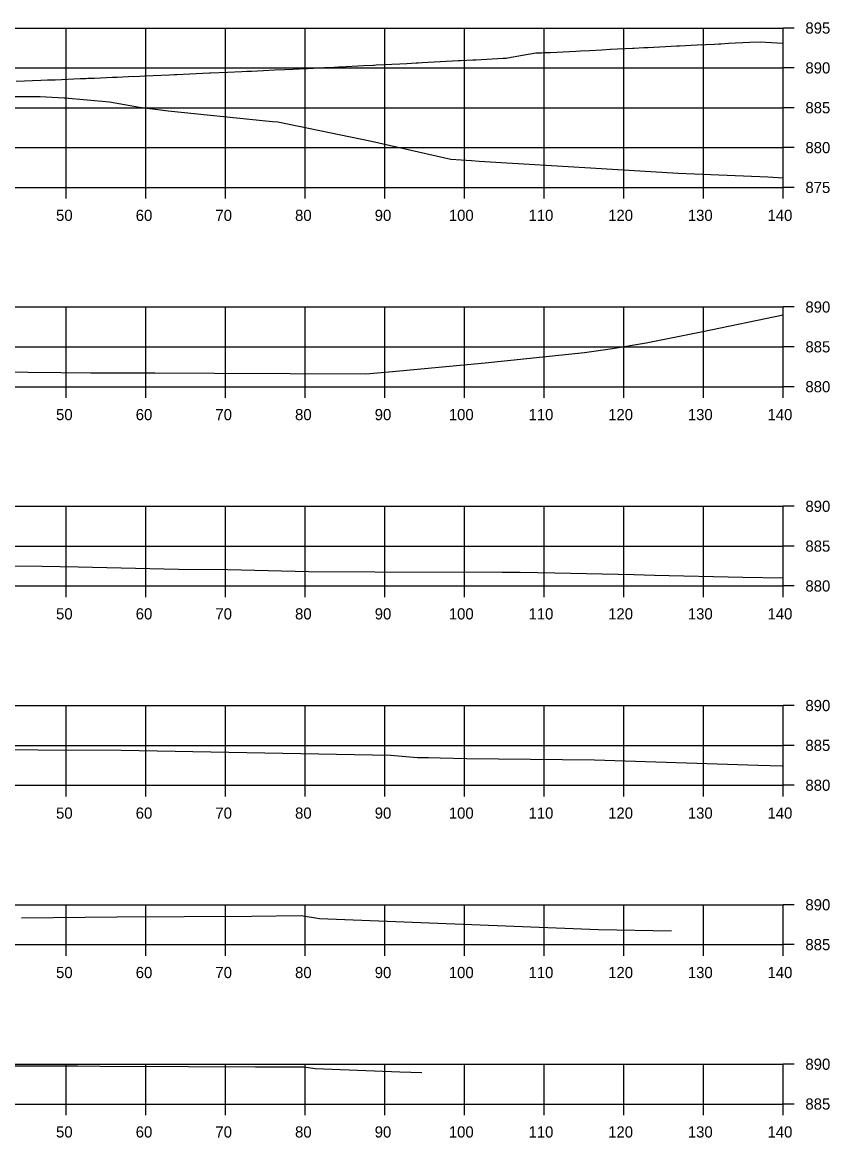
# Model space of a CAD drawing. Extents: x 1098669 to 1198896, y 698679 to 704410.
# Drawn here: x 1110825.7 to 1110927, y 701504.9 to 701644.8 of the extents above; entities that cross this region are included whole.
import ezdxf

# ---------------------------------------------------------------- set-up
doc = ezdxf.new("R2010")
doc.units = 0
for name, color, linetype in [('Proposed Surface', 7, 'Continuous'), ('R_Axis', 7, 'Continuous'), ('R_Axis Annot', 7, 'Continuous'), ('R_Fin Surface', 7, 'Continuous'), ('R_Grid', 7, 'Continuous')]:
    doc.layers.add(name, color=color, linetype=linetype)

msp = doc.modelspace()

# ---------------------------------------------------------------- linework, layer by layer
at = {"layer": 'Proposed Surface'}
for points in [[(1110817.22, 701635.54), (1110827.92, 701635.53), (1110830.92, 701635.39), (1110830.94, 701635.39), (1110831, 701635.38), (1110836.59, 701634.87), (1110840.38, 701634.2), (1110843.97, 701633.73), (1110856.25, 701632.5), (1110857.09, 701632.4), (1110857.75, 701632.37), (1110869.48, 701629.95), (1110879.45, 701627.66), (1110882.06, 701627.52), (1110883.01, 701627.44), (1110898.35, 701626.52), (1110908.01, 701625.93), (1110919.25, 701625.46), (1110921.16, 701625.35)], [(1110818.1, 701601.03), (1110826.42, 701600.95), (1110830.49, 701600.91), (1110834.28, 701600.89), (1110842.32, 701600.86), (1110849.78, 701600.82), (1110868.77, 701600.75), (1110870.23, 701600.87), (1110871.69, 701601.01), (1110883.76, 701602.12), (1110896.24, 701603.43), (1110899.73, 701603.92), (1110903.98, 701604.64), (1110911.07, 701606.06), (1110921.16, 701608.16)], [(1110805.54, 701576.75), (1110828.16, 701576.6), (1110832.68, 701576.55), (1110845.26, 701576.24), (1110851.45, 701576.18), (1110861.57, 701575.94), (1110869.92, 701575.91), (1110885.89, 701575.86), (1110888.15, 701575.85), (1110892.5, 701575.79), (1110902.42, 701575.55), (1110905.02, 701575.5), (1110916.12, 701575.24), (1110921.16, 701575.14)], [(1110817.14, 701553.61), (1110838.07, 701553.53), (1110871.9, 701552.9), (1110875.26, 701552.62), (1110876.64, 701552.61), (1110878.11, 701552.57), (1110881.41, 701552.48), (1110897.47, 701552.3), (1110918.01, 701551.63), (1110921.05, 701551.56), (1110921.16, 701551.56)], [(1110825.58, 701532.51), (1110837.52, 701532.63), (1110854.44, 701532.69), (1110860.66, 701532.77), (1110862.96, 701532.42), (1110898.01, 701531.02), (1110907.14, 701530.86)], [(1110820.41, 701513.93), (1110832.6, 701513.91), (1110835.45, 701513.88), (1110846.52, 701513.83), (1110854.92, 701513.81), (1110861.01, 701513.79), (1110862.44, 701513.57), (1110873.07, 701513.15), (1110875.83, 701513.1)]]:
    msp.add_lwpolyline(points, dxfattribs=at)
at = {"layer": 'R_Axis'}
for p, q in [((1110921.16, 701624.13), (1110921.16, 701644.13)), ((1110922.56, 701644.13), (1110921.16, 701644.13)), ((1110922.56, 701639.13), (1110921.16, 701639.13)), ((1110922.56, 701634.13), (1110921.16, 701634.13)), ((1110922.56, 701629.13), (1110921.16, 701629.13)), ((1110641.16, 701624.13), (1110921.16, 701624.13)), ((1110831.16, 701622.73), (1110831.16, 701624.13)), ((1110841.16, 701622.73), (1110841.16, 701624.13)), ((1110851.16, 701622.73), (1110851.16, 701624.13)), ((1110861.16, 701622.73), (1110861.16, 701624.13)), ((1110871.16, 701622.73), (1110871.16, 701624.13)), ((1110881.16, 701622.73), (1110881.16, 701624.13)), ((1110891.16, 701622.73), (1110891.16, 701624.13)), ((1110901.16, 701622.73), (1110901.16, 701624.13)), ((1110911.16, 701622.73), (1110911.16, 701624.13)), ((1110921.16, 701622.73), (1110921.16, 701624.13)), ((1110922.56, 701624.13), (1110921.16, 701624.13)), ((1110921.16, 701599.13), (1110921.16, 701609.13)), ((1110922.56, 701609.13), (1110921.16, 701609.13)), ((1110922.56, 701604.13), (1110921.16, 701604.13)), ((1110641.16, 701599.13), (1110921.16, 701599.13)), ((1110831.16, 701597.73), (1110831.16, 701599.13)), ((1110841.16, 701597.73), (1110841.16, 701599.13)), ((1110851.16, 701597.73), (1110851.16, 701599.13)), ((1110861.16, 701597.73), (1110861.16, 701599.13)), ((1110871.16, 701597.73), (1110871.16, 701599.13)), ((1110881.16, 701597.73), (1110881.16, 701599.13)), ((1110891.16, 701597.73), (1110891.16, 701599.13)), ((1110901.16, 701597.73), (1110901.16, 701599.13)), ((1110911.16, 701597.73), (1110911.16, 701599.13)), ((1110921.16, 701597.73), (1110921.16, 701599.13)), ((1110922.56, 701599.13), (1110921.16, 701599.13)), ((1110921.16, 701574.13), (1110921.16, 701584.13)), ((1110922.56, 701584.13), (1110921.16, 701584.13)), ((1110922.56, 701579.13), (1110921.16, 701579.13)), ((1110641.16, 701574.13), (1110921.16, 701574.13)), ((1110831.16, 701572.73), (1110831.16, 701574.13)), ((1110841.16, 701572.73), (1110841.16, 701574.13)), ((1110851.16, 701572.73), (1110851.16, 701574.13)), ((1110861.16, 701572.73), (1110861.16, 701574.13)), ((1110871.16, 701572.73), (1110871.16, 701574.13)), ((1110881.16, 701572.73), (1110881.16, 701574.13)), ((1110891.16, 701572.73), (1110891.16, 701574.13)), ((1110901.16, 701572.73), (1110901.16, 701574.13)), ((1110911.16, 701572.73), (1110911.16, 701574.13)), ((1110921.16, 701572.73), (1110921.16, 701574.13)), ((1110922.56, 701574.13), (1110921.16, 701574.13)), ((1110921.16, 701549.13), (1110921.16, 701559.13)), ((1110922.56, 701559.13), (1110921.16, 701559.13)), ((1110922.56, 701554.13), (1110921.16, 701554.13)), ((1110641.16, 701549.13), (1110921.16, 701549.13)), ((1110831.16, 701547.73), (1110831.16, 701549.13)), ((1110841.16, 701547.73), (1110841.16, 701549.13)), ((1110851.16, 701547.73), (1110851.16, 701549.13)), ((1110861.16, 701547.73), (1110861.16, 701549.13)), ((1110871.16, 701547.73), (1110871.16, 701549.13)), ((1110881.16, 701547.73), (1110881.16, 701549.13)), ((1110891.16, 701547.73), (1110891.16, 701549.13)), ((1110901.16, 701547.73), (1110901.16, 701549.13)), ((1110911.16, 701547.73), (1110911.16, 701549.13)), ((1110921.16, 701547.73), (1110921.16, 701549.13)), ((1110922.56, 701549.13), (1110921.16, 701549.13)), ((1110921.16, 701529.13), (1110921.16, 701534.13)), ((1110922.56, 701534.13), (1110921.16, 701534.13)), ((1110641.16, 701529.13), (1110921.16, 701529.13)), ((1110831.16, 701527.73), (1110831.16, 701529.13)), ((1110841.16, 701527.73), (1110841.16, 701529.13)), ((1110851.16, 701527.73), (1110851.16, 701529.13)), ((1110861.16, 701527.73), (1110861.16, 701529.13)), ((1110871.16, 701527.73), (1110871.16, 701529.13)), ((1110881.16, 701527.73), (1110881.16, 701529.13)), ((1110891.16, 701527.73), (1110891.16, 701529.13)), ((1110901.16, 701527.73), (1110901.16, 701529.13)), ((1110911.16, 701527.73), (1110911.16, 701529.13)), ((1110921.16, 701527.73), (1110921.16, 701529.13)), ((1110922.56, 701529.13), (1110921.16, 701529.13)), ((1110921.16, 701509.13), (1110921.16, 701514.13)), ((1110922.56, 701514.13), (1110921.16, 701514.13)), ((1110641.16, 701509.13), (1110921.16, 701509.13)), ((1110831.16, 701507.73), (1110831.16, 701509.13)), ((1110841.16, 701507.73), (1110841.16, 701509.13)), ((1110851.16, 701507.73), (1110851.16, 701509.13)), ((1110861.16, 701507.73), (1110861.16, 701509.13)), ((1110871.16, 701507.73), (1110871.16, 701509.13)), ((1110881.16, 701507.73), (1110881.16, 701509.13)), ((1110891.16, 701507.73), (1110891.16, 701509.13)), ((1110901.16, 701507.73), (1110901.16, 701509.13)), ((1110911.16, 701507.73), (1110911.16, 701509.13)), ((1110921.16, 701507.73), (1110921.16, 701509.13)), ((1110922.56, 701509.13), (1110921.16, 701509.13))]:
    msp.add_line(p, q, dxfattribs=at)
at = {"layer": 'R_Fin Surface'}
msp.add_lwpolyline([(1110824.9, 701637.45), (1110828.01, 701637.58), (1110828.82, 701637.61), (1110828.84, 701637.61), (1110828.91, 701637.61), (1110829.81, 701637.65), (1110832.94, 701637.78), (1110833.66, 701637.81), (1110833.91, 701637.82), (1110834.73, 701637.85), (1110836.97, 701637.95), (1110837.58, 701637.97), (1110839.01, 701638.03), (1110840.36, 701638.09), (1110841.02, 701638.12), (1110842.1, 701638.17), (1110844.13, 701638.26), (1110844.72, 701638.29), (1110845.08, 701638.3), (1110846.71, 701638.38), (1110849.15, 701638.49), (1110849.2, 701638.49), (1110849.27, 701638.49), (1110851.42, 701638.59), (1110853.24, 701638.68), (1110853.85, 701638.71), (1110854.44, 701638.73), (1110855.94, 701638.8), (1110857.34, 701638.87), (1110858.61, 701638.93), (1110859.63, 701638.98), (1110860.4, 701639.02), (1110861.46, 701639.07), (1110863.58, 701639.17), (1110864.85, 701639.24), (1110865.34, 701639.26), (1110865.6, 701639.27), (1110868.51, 701639.42), (1110869.76, 701639.48), (1110869.85, 701639.49), (1110870.09, 701639.5), (1110873.06, 701639.65), (1110873.93, 701639.7), (1110875.09, 701639.76), (1110875.37, 701639.77), (1110875.87, 701639.8), (1110878.13, 701639.92), (1110880.41, 701640.04), (1110880.68, 701640.05), (1110882.22, 701640.13), (1110882.35, 701640.14), (1110882.59, 701640.15), (1110886.03, 701640.34), (1110886.03, 701640.34), (1110886.39, 701640.36), (1110886.58, 701640.39), (1110888.47, 701640.72), (1110890.14, 701641), (1110890.85, 701641.03), (1110891.12, 701641.05), (1110891.41, 701641.06), (1110891.79, 701641.08), (1110891.98, 701641.08), (1110895.14, 701641.24), (1110895.73, 701641.27), (1110896.84, 701641.33), (1110898.42, 701641.41), (1110899.45, 701641.46), (1110902.24, 701641.6), (1110902.3, 701641.61), (1110902.32, 701641.61), (1110902.46, 701641.61), (1110903.68, 701641.68), (1110903.79, 701641.68), (1110904.22, 701641.7), (1110907.81, 701641.88), (1110907.93, 701641.89), (1110908.16, 701641.9), (1110910.39, 701642.02), (1110912.55, 701642.12), (1110913.09, 701642.15), (1110913.36, 701642.16), (1110914.3, 701642.21), (1110916.98, 701642.35), (1110918.3, 701642.41), (1110918.96, 701642.37), (1110921.16, 701642.22)], dxfattribs=at)
at = {"layer": 'R_Grid'}
for p, q in [((1110641.16, 701644.13), (1110921.16, 701644.13)), ((1110831.16, 701624.13), (1110831.16, 701644.13)), ((1110841.16, 701624.13), (1110841.16, 701644.13)), ((1110851.16, 701624.13), (1110851.16, 701644.13)), ((1110861.16, 701624.13), (1110861.16, 701644.13)), ((1110871.16, 701624.13), (1110871.16, 701644.13)), ((1110881.16, 701624.13), (1110881.16, 701644.13)), ((1110891.16, 701624.13), (1110891.16, 701644.13)), ((1110901.16, 701624.13), (1110901.16, 701644.13)), ((1110911.16, 701624.13), (1110911.16, 701644.13)), ((1110921.16, 701624.13), (1110921.16, 701644.13)), ((1110641.16, 701639.13), (1110921.16, 701639.13)), ((1110641.16, 701634.13), (1110921.16, 701634.13)), ((1110641.16, 701629.13), (1110921.16, 701629.13)), ((1110641.16, 701624.13), (1110921.16, 701624.13)), ((1110641.16, 701609.13), (1110921.16, 701609.13)), ((1110831.16, 701599.13), (1110831.16, 701609.13)), ((1110841.16, 701599.13), (1110841.16, 701609.13)), ((1110851.16, 701599.13), (1110851.16, 701609.13)), ((1110861.16, 701599.13), (1110861.16, 701609.13)), ((1110871.16, 701599.13), (1110871.16, 701609.13)), ((1110881.16, 701599.13), (1110881.16, 701609.13)), ((1110891.16, 701599.13), (1110891.16, 701609.13)), ((1110901.16, 701599.13), (1110901.16, 701609.13)), ((1110911.16, 701599.13), (1110911.16, 701609.13)), ((1110921.16, 701599.13), (1110921.16, 701609.13)), ((1110641.16, 701604.13), (1110921.16, 701604.13)), ((1110641.16, 701599.13), (1110921.16, 701599.13)), ((1110641.16, 701584.13), (1110921.16, 701584.13)), ((1110831.16, 701574.13), (1110831.16, 701584.13)), ((1110841.16, 701574.13), (1110841.16, 701584.13)), ((1110851.16, 701574.13), (1110851.16, 701584.13)), ((1110861.16, 701574.13), (1110861.16, 701584.13)), ((1110871.16, 701574.13), (1110871.16, 701584.13)), ((1110881.16, 701574.13), (1110881.16, 701584.13)), ((1110891.16, 701574.13), (1110891.16, 701584.13)), ((1110901.16, 701574.13), (1110901.16, 701584.13)), ((1110911.16, 701574.13), (1110911.16, 701584.13)), ((1110921.16, 701574.13), (1110921.16, 701584.13)), ((1110641.16, 701579.13), (1110921.16, 701579.13)), ((1110641.16, 701574.13), (1110921.16, 701574.13)), ((1110641.16, 701559.13), (1110921.16, 701559.13)), ((1110831.16, 701549.13), (1110831.16, 701559.13)), ((1110841.16, 701549.13), (1110841.16, 701559.13)), ((1110851.16, 701549.13), (1110851.16, 701559.13)), ((1110861.16, 701549.13), (1110861.16, 701559.13)), ((1110871.16, 701549.13), (1110871.16, 701559.13)), ((1110881.16, 701549.13), (1110881.16, 701559.13)), ((1110891.16, 701549.13), (1110891.16, 701559.13)), ((1110901.16, 701549.13), (1110901.16, 701559.13)), ((1110911.16, 701549.13), (1110911.16, 701559.13)), ((1110921.16, 701549.13), (1110921.16, 701559.13)), ((1110641.16, 701554.13), (1110921.16, 701554.13)), ((1110641.16, 701549.13), (1110921.16, 701549.13)), ((1110641.16, 701534.13), (1110921.16, 701534.13)), ((1110831.16, 701529.13), (1110831.16, 701534.13)), ((1110841.16, 701529.13), (1110841.16, 701534.13)), ((1110851.16, 701529.13), (1110851.16, 701534.13)), ((1110861.16, 701529.13), (1110861.16, 701534.13)), ((1110871.16, 701529.13), (1110871.16, 701534.13)), ((1110881.16, 701529.13), (1110881.16, 701534.13)), ((1110891.16, 701529.13), (1110891.16, 701534.13)), ((1110901.16, 701529.13), (1110901.16, 701534.13)), ((1110911.16, 701529.13), (1110911.16, 701534.13)), ((1110921.16, 701529.13), (1110921.16, 701534.13)), ((1110641.16, 701529.13), (1110921.16, 701529.13)), ((1110641.16, 701514.13), (1110921.16, 701514.13)), ((1110831.16, 701509.13), (1110831.16, 701514.13)), ((1110841.16, 701509.13), (1110841.16, 701514.13)), ((1110851.16, 701509.13), (1110851.16, 701514.13)), ((1110861.16, 701509.13), (1110861.16, 701514.13)), ((1110871.16, 701509.13), (1110871.16, 701514.13)), ((1110881.16, 701509.13), (1110881.16, 701514.13)), ((1110891.16, 701509.13), (1110891.16, 701514.13)), ((1110901.16, 701509.13), (1110901.16, 701514.13)), ((1110911.16, 701509.13), (1110911.16, 701514.13)), ((1110921.16, 701509.13), (1110921.16, 701514.13)), ((1110641.16, 701509.13), (1110921.16, 701509.13))]:
    msp.add_line(p, q, dxfattribs=at)

# ---------------------------------------------------------------- texts
at = {"layer": 'R_Axis Annot'}
for s, p in [('895', (1110923.96, 701643.43)), ('890', (1110923.96, 701638.43)), ('885', (1110923.96, 701633.43)), ('880', (1110923.96, 701628.43)), ('875', (1110923.96, 701623.43)), ('50', (1110829.9, 701619.93)), ('60', (1110839.9, 701619.93)), ('70', (1110849.9, 701619.93)), ('80', (1110859.9, 701619.93)), ('90', (1110869.9, 701619.93)), ('100', (1110879.2, 701619.93)), ('110', (1110889.2, 701619.93)), ('120', (1110899.2, 701619.93)), ('130', (1110909.2, 701619.93)), ('140', (1110919.2, 701619.93)), ('890', (1110923.96, 701608.43)), ('885', (1110923.96, 701603.43)), ('880', (1110923.96, 701598.43)), ('50', (1110829.9, 701594.93)), ('60', (1110839.9, 701594.93)), ('70', (1110849.9, 701594.93)), ('80', (1110859.9, 701594.93)), ('90', (1110869.9, 701594.93)), ('100', (1110879.2, 701594.93)), ('110', (1110889.2, 701594.93)), ('120', (1110899.2, 701594.93)), ('130', (1110909.2, 701594.93)), ('140', (1110919.2, 701594.93)), ('890', (1110923.96, 701583.43)), ('885', (1110923.96, 701578.43)), ('880', (1110923.96, 701573.43)), ('50', (1110829.9, 701569.93)), ('60', (1110839.9, 701569.93)), ('70', (1110849.9, 701569.93)), ('80', (1110859.9, 701569.93)), ('90', (1110869.9, 701569.93)), ('100', (1110879.2, 701569.93)), ('110', (1110889.2, 701569.93)), ('120', (1110899.2, 701569.93)), ('130', (1110909.2, 701569.93)), ('140', (1110919.2, 701569.93)), ('890', (1110923.96, 701558.43)), ('885', (1110923.96, 701553.43)), ('880', (1110923.96, 701548.43)), ('50', (1110829.9, 701544.93)), ('60', (1110839.9, 701544.93)), ('70', (1110849.9, 701544.93)), ('80', (1110859.9, 701544.93)), ('90', (1110869.9, 701544.93)), ('100', (1110879.2, 701544.93)), ('110', (1110889.2, 701544.93)), ('120', (1110899.2, 701544.93)), ('130', (1110909.2, 701544.93)), ('140', (1110919.2, 701544.93)), ('890', (1110923.96, 701533.43)), ('885', (1110923.96, 701528.43)), ('50', (1110829.9, 701524.93)), ('60', (1110839.9, 701524.93)), ('70', (1110849.9, 701524.93)), ('80', (1110859.9, 701524.93)), ('90', (1110869.9, 701524.93)), ('100', (1110879.2, 701524.93)), ('110', (1110889.2, 701524.93)), ('120', (1110899.2, 701524.93)), ('130', (1110909.2, 701524.93)), ('140', (1110919.2, 701524.93)), ('890', (1110923.96, 701513.43)), ('885', (1110923.96, 701508.43)), ('50', (1110829.9, 701504.93)), ('60', (1110839.9, 701504.93)), ('70', (1110849.9, 701504.93)), ('80', (1110859.9, 701504.93)), ('90', (1110869.9, 701504.93)), ('100', (1110879.2, 701504.93)), ('110', (1110889.2, 701504.93)), ('120', (1110899.2, 701504.93)), ('130', (1110909.2, 701504.93)), ('140', (1110919.2, 701504.93))]:
    msp.add_text(s, height=1.4, dxfattribs=at).set_placement(p)

doc.saveas('drawing.dxf')
